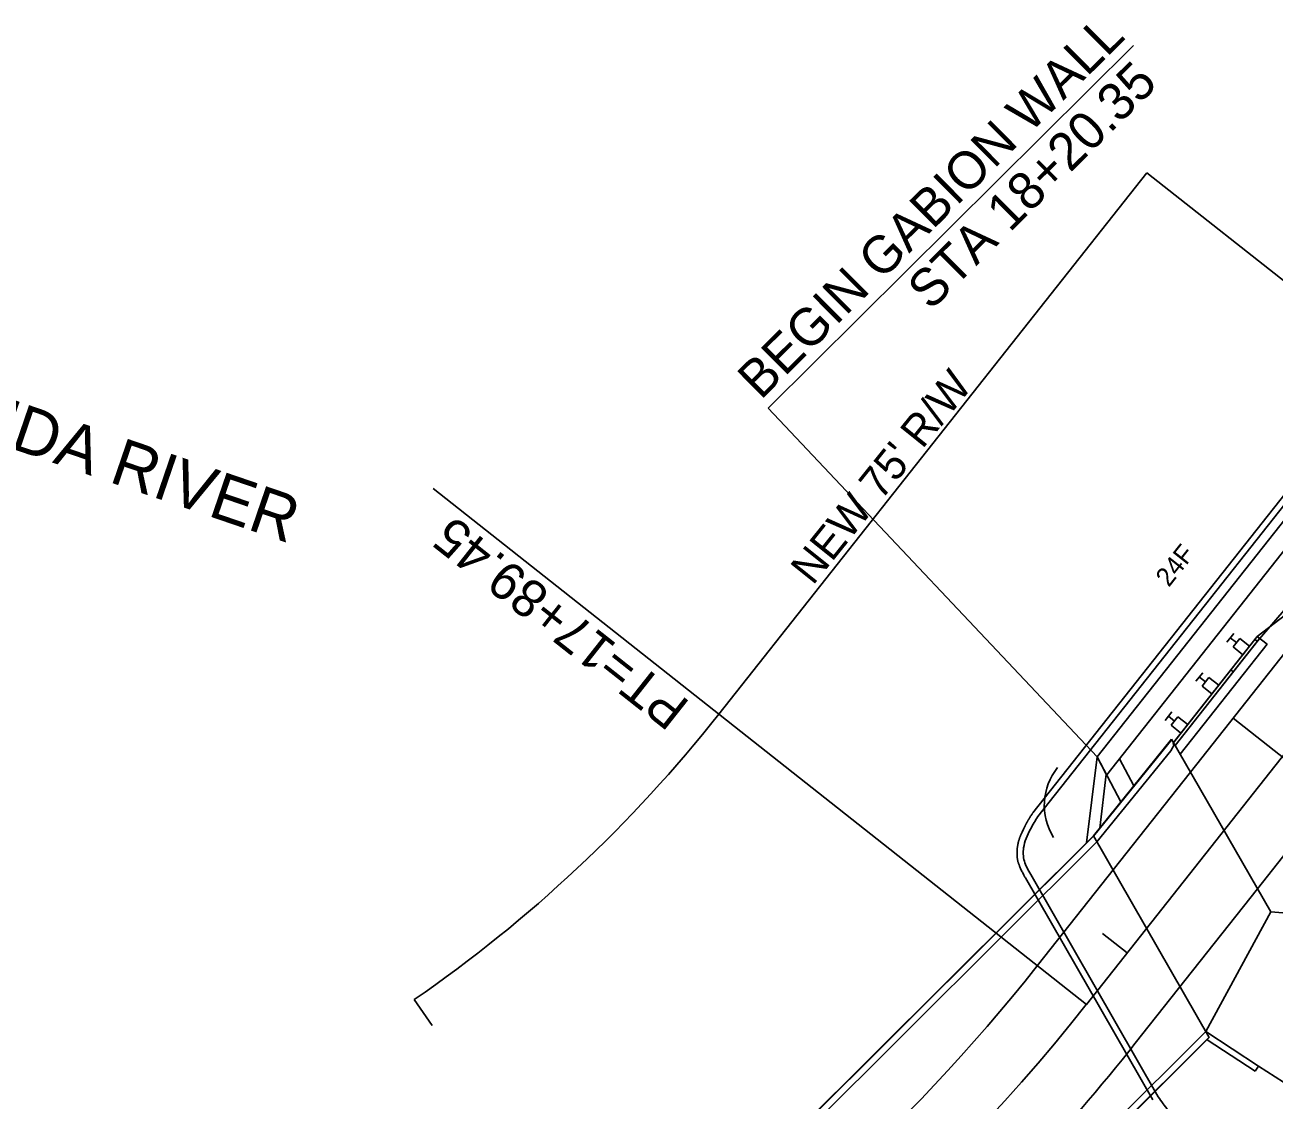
# Model space of a CAD drawing. Extents: x 1539042 to 1541327, y 1198578 to 1200629.
# Drawn here: x 1539977.1 to 1540177.1, y 1199475.4 to 1199647.6 of the extents above; entities that cross this region are included whole.
import ezdxf

# ---------------------------------------------------------------- set-up
doc = ezdxf.new("R2010")
doc.units = 0
for name, color, linetype in [('BR_CONCRETE', 7, 'Continuous'), ('BR_PROPOSED_TRAVELWAY', 7, 'Continuous'), ('RD_HC_CL_Rel', 7, 'Continuous'), ('RD_HC_Data', 7, 'Continuous'), ('RD_HC_Data_Tic', 7, 'Continuous'), ('RD_PD_ALT1_TX', 7, 'Continuous'), ('RD_PD_BOC', 7, 'Continuous'), ('RD_PD_CstnLmt', 7, 'Continuous'), ('RD_PD_CstnLmt_TX', 7, 'Continuous'), ('RD_PD_DR_ErosCtrl', 7, 'Continuous'), ('RD_PD_Driveway', 7, 'Continuous'), ('RD_PD_EOP', 7, 'Continuous'), ('RD_PD_Final_TrvlWay', 7, 'Continuous'), ('RD_PD_Final_TX', 7, 'Continuous'), ('RD_PD_FOC', 7, 'Continuous'), ('RD_PD_GR', 7, 'Continuous'), ('RD_PD_PaveShd', 7, 'Continuous'), ('RD_PD_RW', 7, 'Continuous'), ('RD_PD_WallFill', 7, 'Continuous')]:
    doc.layers.add(name, color=color, linetype=linetype)

# ---------------------------------------------------------------- blocks, each defined once
blk = doc.blocks.new('Guardrail_MTBBC2_Transition')
at = {"layer": 'RD_PD_GR'}
for p, q in [((3.875, 3.75), (2.125, 3.75)), ((2.125, 0.5), (2.125, 2.5)), ((2.125, 2.5), (3.875, 2.5)), ((3, 2.5), (3, 3.75)), ((3.875, 2.5), (3.875, 0.5)), ((11.875, 3.75), (10.125, 3.75)), ((10.125, 0.5), (10.125, 2.5)), ((10.125, 2.5), (11.875, 2.5)), ((11, 2.5), (11, 3.75)), ((11.875, 2.5), (11.875, 0.5)), ((19.875, 3.75), (18.125, 3.75)), ((18.125, 0.5), (18.125, 2.5)), ((18.125, 2.5), (19.875, 2.5)), ((19, 2.5), (19, 3.75)), ((19.875, 2.5), (19.875, 0.5)), ((0, 0.5), (0, 0)), ((21.25, 0.5), (0, 0.5)), ((0, 0), (21.25, 0)), ((3.875, 0.5), (2.125, 0.5)), ((11.875, 0.5), (10.125, 0.5)), ((15, 0.5), (15, 0)), ((19.875, 0.5), (18.125, 0.5)), ((21.25, 0), (21.25, 0.5))]:
    blk.add_line(p, q, dxfattribs=at)

msp = doc.modelspace()

# ---------------------------------------------------------------- linework, layer by layer
at = {"layer": 'BR_CONCRETE'}
for p, q in [((1540148.21, 1199517.71), (1540160.73, 1199533.19)), ((1540148.25, 1199517.64), (1540160.77, 1199533.12)), ((1540176.63, 1199505.52), (1540160.73, 1199533.19)), ((1540148.77, 1199516.74), (1540160.63, 1199531.35)), ((1540160.63, 1199531.35), (1540161.17, 1199532.42)), ((1540148.8, 1199530.38), (1540147.11, 1199516.61)), ((1540150.28, 1199527.59), (1540148.8, 1199530.38)), ((1540150.28, 1199527.59), (1540149.22, 1199518.96)), ((1540077.64, 1199447.44), (1540148.21, 1199517.71)), ((1540077.68, 1199447.36), (1540148.25, 1199517.64)), ((1540078.2, 1199446.47), (1540148.77, 1199516.74)), ((1540166.77, 1199485.39), (1540148.21, 1199517.71)), ((1540166.22, 1199486.37), (1540176.63, 1199505.52)), ((1540095.64, 1199416.09), (1540166.22, 1199486.37)), ((1540096.16, 1199415.2), (1540166.73, 1199485.47)), ((1540096.2, 1199415.12), (1540166.77, 1199485.39)), ((1540166.22, 1199486.37), (1540174.66, 1199480.84)), ((1540166.42, 1199485.04), (1540174.11, 1199480)), ((1540174.66, 1199480.84), (1540174.11, 1199480))]:
    msp.add_line(p, q, dxfattribs=at)
at = {"layer": 'BR_PROPOSED_TRAVELWAY'}
for p, q in [((1540163.75, 1199527.93), (1540139.23, 1199496.89)), ((1540174.48, 1199509.25), (1540154.92, 1199484.5))]:
    msp.add_line(p, q, dxfattribs=at)
for radius, start in [(290, 301.8034), (310, 301.6792)]:
    msp.add_arc((1539911.68, 1199676.68), radius, start, 321.687, dxfattribs=at)
at = {"layer": 'RD_HC_CL_Rel'}
msp.add_line((1540147.08, 1199490.69), (1540235.28, 1199602.33), dxfattribs=at)
msp.add_arc((1539911.68, 1199676.68), 300, 272.8619, 321.687, dxfattribs=at)
at = {"layer": 'RD_HC_Data'}
msp.add_line((1540147.08, 1199490.69), (1540042.49, 1199573.33), dxfattribs=at)
at = {"layer": 'RD_HC_Data_Tic'}
msp.add_line((1540153.62, 1199498.98), (1540149.69, 1199502.08), dxfattribs=at)
at = {"layer": 'RD_PD_ALT1_TX'}
msp.add_line((1540170.57, 1199536.56), (1540186.26, 1199524.16), dxfattribs=at)
at = {"layer": 'RD_PD_BOC'}
msp.add_line((1540161.03, 1199532.67), (1540174.44, 1199549.64), dxfattribs=at)
at = {"layer": 'RD_PD_CstnLmt'}
for p, q in [((1540139.32, 1199520.8), (1540215.86, 1199617.68)), ((1540158.58, 1199475.93), (1540138.18, 1199511.5))]:
    msp.add_line(p, q, dxfattribs=at)
for points in [[(1540139.32, 1199520.8), (1540138.72, 1199519.85), (1540138.14, 1199518.8), (1540137.42, 1199517.27), (1540137.04, 1199515.8), (1540136.98, 1199514.76), (1540137.15, 1199513.68), (1540138.18, 1199511.5)], [(1540158.58, 1199475.93), (1540159.36, 1199474.81), (1540160.18, 1199473.82), (1540161.14, 1199472.91), (1540162.25, 1199471.89)]]:
    msp.add_spline(points, degree=3, dxfattribs=at)
at = {"layer": 'RD_PD_DR_ErosCtrl'}
for p, q in [((1540138.53, 1199521.42), (1540215.08, 1199618.3)), ((1540157.72, 1199475.43), (1540137.31, 1199511))]:
    msp.add_line(p, q, dxfattribs=at)
msp.add_arc((1540150.09, 1199522.59), 9.74, 141.434, 211.687, dxfattribs=at)
msp.add_open_spline([(1540138.49, 1199521.36), (1540138.36, 1199521.17), (1540138.24, 1199520.99), (1540138.07, 1199520.71), (1540138.01, 1199520.62), (1540137.93, 1199520.48), (1540137.9, 1199520.44), (1540137.87, 1199520.39), (1540137.87, 1199520.38), (1540137.86, 1199520.38), (1540137.86, 1199520.38), (1540137.86, 1199520.38), (1540137.86, 1199520.38), (1540137.86, 1199520.38), (1540137.86, 1199520.38), (1540137.86, 1199520.37), (1540137.85, 1199520.35), (1540137.83, 1199520.33), (1540137.81, 1199520.29), (1540137.8, 1199520.27), (1540137.72, 1199520.14), (1540137.67, 1199520.04), (1540137.56, 1199519.84), (1540137.5, 1199519.75), (1540137.4, 1199519.55), (1540137.35, 1199519.46), (1540137.29, 1199519.34), (1540137.28, 1199519.32), (1540137.26, 1199519.29), (1540137.26, 1199519.28), (1540137.25, 1199519.26), (1540137.25, 1199519.26), (1540137.25, 1199519.26), (1540137.25, 1199519.26), (1540137.25, 1199519.26), (1540137.25, 1199519.25), (1540137.24, 1199519.24), (1540137.21, 1199519.18), (1540137.18, 1199519.13), (1540137.05, 1199518.88), (1540136.96, 1199518.68), (1540136.77, 1199518.28), (1540136.68, 1199518.08), (1540136.57, 1199517.83), (1540136.55, 1199517.77), (1540136.52, 1199517.71), (1540136.51, 1199517.69), (1540136.51, 1199517.67), (1540136.5, 1199517.66), (1540136.5, 1199517.65), (1540136.5, 1199517.65), (1540136.5, 1199517.65), (1540136.5, 1199517.65), (1540136.5, 1199517.65), (1540136.5, 1199517.65), (1540136.48, 1199517.62), (1540136.47, 1199517.59), (1540136.41, 1199517.44), (1540136.37, 1199517.32), (1540136.29, 1199517.08), (1540136.26, 1199516.96), (1540136.2, 1199516.72), (1540136.17, 1199516.61), (1540136.12, 1199516.38), (1540136.1, 1199516.26), (1540136.07, 1199516.09), (1540136.06, 1199516.04), (1540136.05, 1199515.98), (1540136.05, 1199515.97), (1540136.05, 1199515.97), (1540136.05, 1199515.96), (1540136.05, 1199515.96), (1540136.05, 1199515.96), (1540136.05, 1199515.96), (1540136.05, 1199515.95), (1540136.04, 1199515.93), (1540136.04, 1199515.9), (1540136.03, 1199515.85), (1540136.03, 1199515.82), (1540136.01, 1199515.66), (1540136, 1199515.53), (1540135.98, 1199515.28), (1540135.98, 1199515.15), (1540135.98, 1199514.97), (1540135.98, 1199514.91), (1540135.98, 1199514.82), (1540135.98, 1199514.79), (1540135.98, 1199514.76), (1540135.98, 1199514.75), (1540135.98, 1199514.73), (1540135.98, 1199514.73), (1540135.98, 1199514.73), (1540135.98, 1199514.73), (1540135.98, 1199514.72), (1540135.98, 1199514.72), (1540135.98, 1199514.71), (1540135.98, 1199514.69), (1540135.99, 1199514.62), (1540135.99, 1199514.56), (1540136, 1199514.44), (1540136, 1199514.38), (1540136.01, 1199514.26), (1540136.02, 1199514.19), (1540136.03, 1199514.06), (1540136.04, 1199513.99), (1540136.07, 1199513.85), (1540136.08, 1199513.78), (1540136.12, 1199513.64), (1540136.13, 1199513.56), (1540136.17, 1199513.45), (1540136.18, 1199513.42), (1540136.2, 1199513.37), (1540136.2, 1199513.36), (1540136.2, 1199513.35), (1540136.21, 1199513.34), (1540136.21, 1199513.34), (1540136.21, 1199513.34), (1540136.21, 1199513.34), (1540136.21, 1199513.34), (1540136.21, 1199513.34), (1540136.21, 1199513.34), (1540136.21, 1199513.34), (1540136.21, 1199513.32), (1540136.24, 1199513.25), (1540136.27, 1199513.18), (1540136.33, 1199513.01), (1540136.37, 1199512.91), (1540136.5, 1199512.59), (1540136.59, 1199512.38), (1540136.79, 1199511.97), (1540136.89, 1199511.77), (1540137.1, 1199511.37), (1540137.21, 1199511.18), (1540137.32, 1199510.99)], degree=3, dxfattribs=at)
at = {"layer": 'RD_PD_Driveway'}
msp.add_line((1540178.63, 1199478.24), (1540174.66, 1199480.84), dxfattribs=at)
at = {"layer": 'RD_PD_EOP'}
for p, q in [((1540176.01, 1199548.4), (1540174.44, 1199549.64)), ((1540162.1, 1199530.8), (1540176.01, 1199548.4))]:
    msp.add_line(p, q, dxfattribs=at)
at = {"layer": 'RD_PD_Final_TrvlWay'}
for p, q in [((1540227.44, 1199608.53), (1540163.75, 1199527.93)), ((1540243.13, 1199596.13), (1540174.48, 1199509.25))]:
    msp.add_line(p, q, dxfattribs=at)
at = {"layer": 'RD_PD_Final_TX'}
for p in [(1540154.64, 1199644.29), (1540148.8, 1199530.38)]:
    msp.add_line(p, (1540096.11, 1199586.24), dxfattribs=at)
at = {"layer": 'RD_PD_FOC'}
msp.add_line((1540161.3, 1199532.2), (1540174.83, 1199549.33), dxfattribs=at)
at = {"layer": 'RD_PD_GR'}
msp.add_line((1540174.47, 1199548.87), (1540184.19, 1199560.25), dxfattribs=at)
at = {"layer": 'RD_PD_PaveShd'}
for p, q in [((1540174.44, 1199549.64), (1540184.47, 1199557.38)), ((1540176.63, 1199505.52), (1540184.36, 1199504.9))]:
    msp.add_line(p, q, dxfattribs=at)
at = {"layer": 'RD_PD_RW'}
for p, q in [((1540088.23, 1199537.19), (1540156.77, 1199623.94)), ((1540190.81, 1199597.04), (1540156.77, 1199623.94)), ((1540042.34, 1199487.31), (1540039.46, 1199491.48))]:
    msp.add_line(p, q, dxfattribs=at)
msp.add_arc((1539911.68, 1199676.68), 225, 304.604, 321.687, dxfattribs=at)
at = {"layer": 'RD_PD_WallFill'}
for p, q in [((1540148.8, 1199530.38), (1540217.04, 1199616.75)), ((1540150.34, 1199527.49), (1540219.39, 1199614.89)), ((1540152.62, 1199523.17), (1540148.8, 1199530.38)), ((1540154.67, 1199525.71), (1540152.37, 1199530.06))]:
    msp.add_line(p, q, dxfattribs=at)

# ---------------------------------------------------------------- block references
at = {"layer": 'RD_PD_RW', "rotation": 51.687032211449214}
msp.add_blockref('Guardrail_MTBBC2_Transition', (1540161.3, 1199532.2), dxfattribs=at)

# ---------------------------------------------------------------- texts
at = {"layer": 'RD_HC_Data'}
for s, height, rotation, p in [('MIDDLE SALUDA RIVER', 7.5, 341.1022, (1539911.29, 1199601.54)), ('PT=17+89.45', 6, 141.687, (1540083.83, 1199539.01))]:
    msp.add_text(s, height=height, rotation=rotation, dxfattribs=at).set_placement(p)
at = {"layer": 'RD_PD_CstnLmt_TX'}
msp.add_text('24F', height=3, rotation=51.687, dxfattribs=at).set_placement((1540160.29, 1199557.43))
at = {"layer": 'RD_PD_Final_TX'}
for s, p in [('BEGIN GABION WALL', (1540094.94, 1199587.41)), ('STA 18+20.35', (1540122.15, 1199601.71))]:
    msp.add_text(s, height=6, rotation=44.7604, dxfattribs=at).set_placement(p)
at = {"layer": 'RD_PD_RW'}
msp.add_text("NEW 75' R/W", height=5, rotation=51.2447, dxfattribs=at).set_placement((1540103.28, 1199557.7))

doc.saveas('drawing.dxf')
